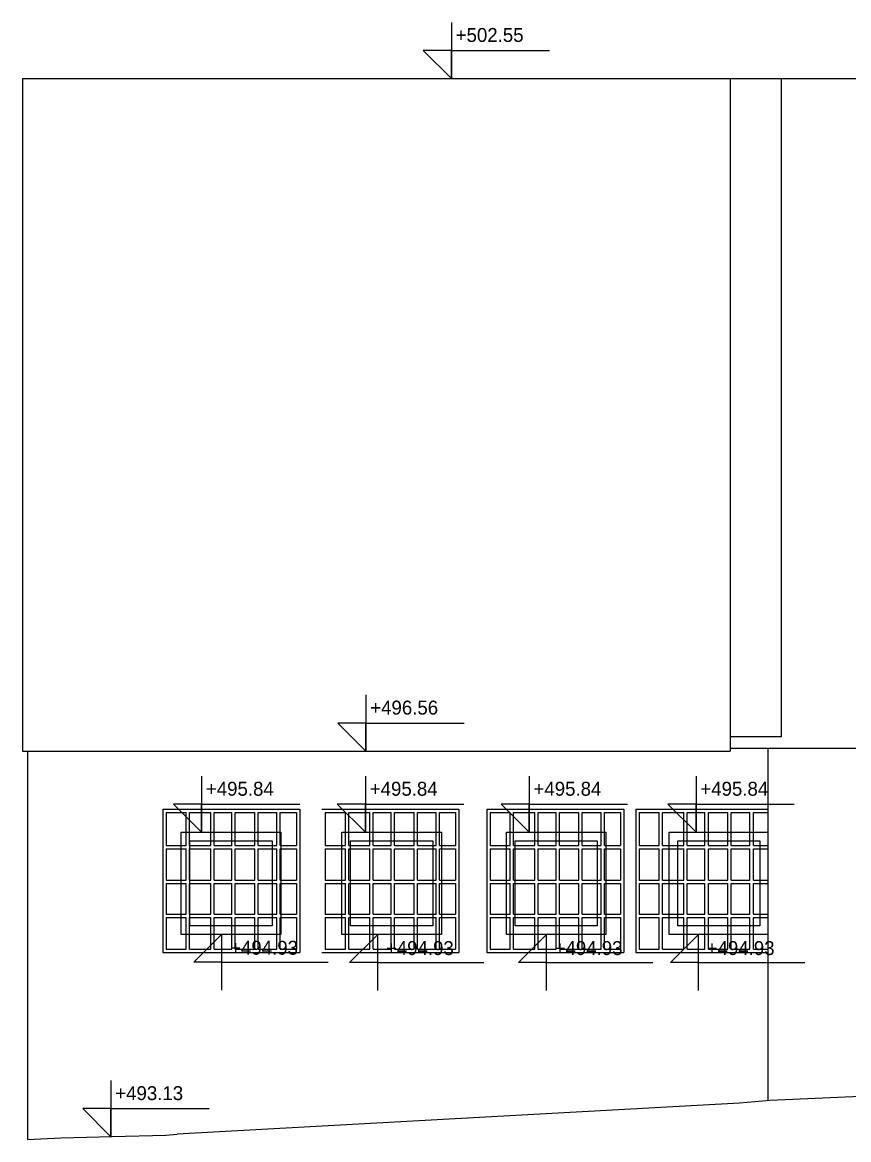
# Model space of a CAD drawing. Extents: x 224 to 311.2, y 493.1 to 511.4.
# Drawn here: x 236.11 to 243.47, y 493.1 to 503.05 of the extents above; entities that cross this region are included whole.
import ezdxf

# ---------------------------------------------------------------- set-up
doc = ezdxf.new("R2010")
doc.units = 0
for name, color, linetype in [('mriz', 7, 'Continuous'), ('okna', 7, 'Continuous'), ('teren', 7, 'Continuous'), ('zakl_tenka', 7, 'Continuous'), ('znaceni', 7, 'Continuous')]:
    doc.layers.add(name, color=color, linetype=linetype)

msp = doc.modelspace()

# ---------------------------------------------------------------- linework, layer by layer
at = {"layer": 'mriz'}
for p, q in [((237.3603, 496.0427), (237.3603, 494.7677)), ((237.3603, 496.0427), (238.5797, 496.0427)), ((237.3903, 496.0127), (237.3903, 495.7213)), ((237.3903, 496.0127), (237.5697, 496.0127)), ((237.5697, 495.7213), (237.5697, 496.0127)), ((237.5997, 496.0127), (237.7886, 496.0127)), ((237.5997, 495.7213), (237.5997, 496.0127)), ((237.7886, 495.7213), (237.7886, 496.0127)), ((237.8186, 496.0127), (237.977, 496.0127)), ((237.8186, 495.7213), (237.8186, 496.0127)), ((237.977, 495.7213), (237.977, 496.0127)), ((238.007, 496.0127), (238.1806, 496.0127)), ((238.007, 495.7213), (238.007, 496.0127)), ((238.1806, 495.7213), (238.1806, 496.0127)), ((238.2106, 496.0127), (238.3773, 496.0127)), ((238.2106, 495.7213), (238.2106, 496.0127)), ((238.3773, 495.7213), (238.3773, 496.0127)), ((238.4073, 496.0127), (238.5506, 496.0127)), ((238.4073, 495.7213), (238.4073, 496.0127)), ((238.5506, 496.0127), (238.5506, 495.7213)), ((238.5797, 496.0427), (238.5797, 494.7677)), ((238.777, 496.0427), (239.9964, 496.0427)), ((238.807, 496.0127), (238.807, 495.7213)), ((238.807, 496.0127), (238.9864, 496.0127)), ((238.9864, 495.7213), (238.9864, 496.0127)), ((239.0164, 496.0127), (239.2053, 496.0127)), ((239.0164, 495.7213), (239.0164, 496.0127)), ((239.2053, 495.7213), (239.2053, 496.0127)), ((239.2353, 496.0127), (239.3937, 496.0127)), ((239.2353, 495.7213), (239.2353, 496.0127)), ((239.3937, 495.7213), (239.3937, 496.0127)), ((239.4237, 496.0127), (239.5973, 496.0127)), ((239.4237, 495.7213), (239.4237, 496.0127)), ((239.5973, 495.7213), (239.5973, 496.0127)), ((239.6273, 496.0127), (239.794, 496.0127)), ((239.6273, 495.7213), (239.6273, 496.0127)), ((239.794, 495.7213), (239.794, 496.0127)), ((239.824, 496.0127), (239.9673, 496.0127)), ((239.824, 495.7213), (239.824, 496.0127)), ((239.9673, 496.0127), (239.9673, 495.7213)), ((239.9964, 496.0427), (239.9964, 494.7677)), ((240.245, 496.0427), (240.245, 494.7677)), ((240.245, 496.0427), (241.4645, 496.0427)), ((240.275, 496.0127), (240.275, 495.7213)), ((240.275, 496.0127), (240.4544, 496.0127)), ((240.4544, 495.7213), (240.4544, 496.0127)), ((240.4844, 496.0127), (240.6733, 496.0127)), ((240.4844, 495.7213), (240.4844, 496.0127)), ((240.6733, 495.7213), (240.6733, 496.0127)), ((240.7033, 496.0127), (240.8617, 496.0127)), ((240.7033, 495.7213), (240.7033, 496.0127)), ((240.8617, 495.7213), (240.8617, 496.0127)), ((240.8917, 496.0127), (241.0653, 496.0127)), ((240.8917, 495.7213), (240.8917, 496.0127)), ((241.0653, 495.7213), (241.0653, 496.0127)), ((241.0953, 496.0127), (241.2621, 496.0127)), ((241.0953, 495.7213), (241.0953, 496.0127)), ((241.2621, 495.7213), (241.2621, 496.0127)), ((241.2921, 496.0127), (241.4353, 496.0127)), ((241.2921, 495.7213), (241.2921, 496.0127)), ((241.4353, 496.0127), (241.4353, 495.7213)), ((241.4645, 496.0427), (241.4645, 494.7677)), ((241.5707, 496.0427), (241.5707, 494.7677)), ((241.5707, 496.0427), (242.7489, 496.0427)), ((241.6007, 496.0127), (241.6007, 495.7213)), ((241.6007, 496.0127), (241.7801, 496.0127)), ((241.7801, 495.7213), (241.7801, 496.0127)), ((241.8101, 496.0127), (241.999, 496.0127)), ((241.8101, 495.7213), (241.8101, 496.0127)), ((241.999, 495.7213), (241.999, 496.0127)), ((242.029, 496.0127), (242.1874, 496.0127)), ((242.029, 495.7213), (242.029, 496.0127)), ((242.1874, 495.7213), (242.1874, 496.0127)), ((242.2174, 496.0127), (242.3911, 496.0127)), ((242.2174, 495.7213), (242.2174, 496.0127)), ((242.3911, 495.7213), (242.3911, 496.0127)), ((242.4211, 496.0127), (242.5878, 496.0127)), ((242.4211, 495.7213), (242.4211, 496.0127)), ((242.5878, 495.7213), (242.5878, 496.0127)), ((242.6178, 496.0127), (242.7489, 496.0127)), ((242.6178, 495.7213), (242.6178, 496.0127)), ((237.3903, 495.7213), (237.5697, 495.7213)), ((237.3903, 495.6913), (237.3903, 495.4127)), ((237.3903, 495.6913), (237.5697, 495.6913)), ((237.5697, 495.4127), (237.5697, 495.6913)), ((237.5997, 495.7213), (237.7886, 495.7213)), ((237.5997, 495.4127), (237.5997, 495.6913)), ((237.5997, 495.6913), (237.7886, 495.6913)), ((237.7886, 495.4127), (237.7886, 495.6913)), ((237.8186, 495.7213), (237.977, 495.7213)), ((237.8186, 495.6913), (237.977, 495.6913)), ((237.8186, 495.4127), (237.8186, 495.6913)), ((237.977, 495.4127), (237.977, 495.6913)), ((238.007, 495.7213), (238.1806, 495.7213)), ((238.007, 495.6913), (238.1806, 495.6913)), ((238.007, 495.4127), (238.007, 495.6913)), ((238.1806, 495.4127), (238.1806, 495.6913)), ((238.2106, 495.7213), (238.3773, 495.7213)), ((238.2106, 495.6913), (238.3773, 495.6913)), ((238.2106, 495.4127), (238.2106, 495.6913)), ((238.3773, 495.4127), (238.3773, 495.6913)), ((238.4073, 495.7213), (238.5506, 495.7213)), ((238.4073, 495.6913), (238.5506, 495.6913)), ((238.4073, 495.4127), (238.4073, 495.6913)), ((238.5506, 495.6913), (238.5506, 495.4127)), ((238.807, 495.7213), (238.9864, 495.7213)), ((238.807, 495.6913), (238.807, 495.4127)), ((238.807, 495.6913), (238.9864, 495.6913)), ((238.9864, 495.4127), (238.9864, 495.6913)), ((239.0164, 495.7213), (239.2053, 495.7213)), ((239.0164, 495.4127), (239.0164, 495.6913)), ((239.0164, 495.6913), (239.2053, 495.6913)), ((239.2053, 495.4127), (239.2053, 495.6913)), ((239.2353, 495.7213), (239.3937, 495.7213)), ((239.2353, 495.6913), (239.3937, 495.6913)), ((239.2353, 495.4127), (239.2353, 495.6913)), ((239.3937, 495.4127), (239.3937, 495.6913)), ((239.4237, 495.7213), (239.5973, 495.7213)), ((239.4237, 495.6913), (239.5973, 495.6913)), ((239.4237, 495.4127), (239.4237, 495.6913)), ((239.5973, 495.4127), (239.5973, 495.6913)), ((239.6273, 495.7213), (239.794, 495.7213)), ((239.6273, 495.6913), (239.794, 495.6913)), ((239.6273, 495.4127), (239.6273, 495.6913)), ((239.794, 495.4127), (239.794, 495.6913)), ((239.824, 495.7213), (239.9673, 495.7213)), ((239.824, 495.6913), (239.9673, 495.6913)), ((239.824, 495.4127), (239.824, 495.6913)), ((239.9673, 495.6913), (239.9673, 495.4127)), ((240.275, 495.7213), (240.4544, 495.7213)), ((240.275, 495.6913), (240.275, 495.4127)), ((240.275, 495.6913), (240.4544, 495.6913)), ((240.4544, 495.4127), (240.4544, 495.6913)), ((240.4844, 495.7213), (240.6733, 495.7213)), ((240.4844, 495.4127), (240.4844, 495.6913)), ((240.4844, 495.6913), (240.6733, 495.6913)), ((240.6733, 495.4127), (240.6733, 495.6913)), ((240.7033, 495.7213), (240.8617, 495.7213)), ((240.7033, 495.6913), (240.8617, 495.6913)), ((240.7033, 495.4127), (240.7033, 495.6913)), ((240.8617, 495.4127), (240.8617, 495.6913)), ((240.8917, 495.7213), (241.0653, 495.7213)), ((240.8917, 495.6913), (241.0653, 495.6913)), ((240.8917, 495.4127), (240.8917, 495.6913)), ((241.0653, 495.4127), (241.0653, 495.6913)), ((241.0953, 495.7213), (241.2621, 495.7213)), ((241.0953, 495.6913), (241.2621, 495.6913)), ((241.0953, 495.4127), (241.0953, 495.6913)), ((241.2621, 495.4127), (241.2621, 495.6913)), ((241.2921, 495.7213), (241.4353, 495.7213)), ((241.2921, 495.6913), (241.4353, 495.6913)), ((241.2921, 495.4127), (241.2921, 495.6913)), ((241.4353, 495.6913), (241.4353, 495.4127)), ((241.6007, 495.7213), (241.7801, 495.7213)), ((241.6007, 495.6913), (241.6007, 495.4127)), ((241.6007, 495.6913), (241.7801, 495.6913)), ((241.7801, 495.4127), (241.7801, 495.6913)), ((241.8101, 495.7213), (241.999, 495.7213)), ((241.8101, 495.4127), (241.8101, 495.6913)), ((241.8101, 495.6913), (241.999, 495.6913)), ((241.999, 495.4127), (241.999, 495.6913)), ((242.029, 495.7213), (242.1874, 495.7213)), ((242.029, 495.6913), (242.1874, 495.6913)), ((242.029, 495.4127), (242.029, 495.6913)), ((242.1874, 495.4127), (242.1874, 495.6913)), ((242.2174, 495.7213), (242.3911, 495.7213)), ((242.2174, 495.6913), (242.3911, 495.6913)), ((242.2174, 495.4127), (242.2174, 495.6913)), ((242.3911, 495.4127), (242.3911, 495.6913)), ((242.4211, 495.7213), (242.5878, 495.7213)), ((242.4211, 495.6913), (242.5878, 495.6913)), ((242.4211, 495.4127), (242.4211, 495.6913)), ((242.5878, 495.4127), (242.5878, 495.6913)), ((242.6178, 495.7213), (242.7489, 495.7213)), ((242.6178, 495.6913), (242.7489, 495.6913)), ((242.6178, 495.4127), (242.6178, 495.6913)), ((237.3903, 495.4127), (237.5697, 495.4127)), ((237.5997, 495.4127), (237.7886, 495.4127)), ((237.8186, 495.4127), (237.977, 495.4127)), ((238.007, 495.4127), (238.1806, 495.4127)), ((238.2106, 495.4127), (238.3773, 495.4127)), ((238.4073, 495.4127), (238.5506, 495.4127)), ((238.807, 495.4127), (238.9864, 495.4127)), ((239.0164, 495.4127), (239.2053, 495.4127)), ((239.2353, 495.4127), (239.3937, 495.4127)), ((239.4237, 495.4127), (239.5973, 495.4127)), ((239.6273, 495.4127), (239.794, 495.4127)), ((239.824, 495.4127), (239.9673, 495.4127)), ((240.275, 495.4127), (240.4544, 495.4127)), ((240.4844, 495.4127), (240.6733, 495.4127)), ((240.7033, 495.4127), (240.8617, 495.4127)), ((240.8917, 495.4127), (241.0653, 495.4127)), ((241.0953, 495.4127), (241.2621, 495.4127)), ((241.2921, 495.4127), (241.4353, 495.4127)), ((241.6007, 495.4127), (241.7801, 495.4127)), ((241.8101, 495.4127), (241.999, 495.4127)), ((242.029, 495.4127), (242.1874, 495.4127)), ((242.2174, 495.4127), (242.3911, 495.4127)), ((242.4211, 495.4127), (242.5878, 495.4127)), ((242.6178, 495.4127), (242.7489, 495.4127)), ((237.3903, 495.3827), (237.3903, 495.1087)), ((237.3903, 495.3827), (237.5697, 495.3827)), ((237.5697, 495.1087), (237.5697, 495.3827)), ((237.5997, 495.3827), (237.7886, 495.3827)), ((237.5997, 495.1087), (237.5997, 495.3827)), ((237.7886, 495.1087), (237.7886, 495.3827)), ((237.8186, 495.3827), (237.977, 495.3827)), ((237.8186, 495.1087), (237.8186, 495.3827)), ((237.977, 495.1087), (237.977, 495.3827)), ((238.007, 495.3827), (238.1806, 495.3827)), ((238.007, 495.1087), (238.007, 495.3827)), ((238.1806, 495.1087), (238.1806, 495.3827)), ((238.2106, 495.3827), (238.3773, 495.3827)), ((238.2106, 495.1087), (238.2106, 495.3827)), ((238.3773, 495.1087), (238.3773, 495.3827)), ((238.4073, 495.3827), (238.5506, 495.3827)), ((238.4073, 495.1087), (238.4073, 495.3827)), ((238.5506, 495.3827), (238.5506, 495.1087)), ((238.807, 495.3827), (238.807, 495.1087)), ((238.807, 495.3827), (238.9864, 495.3827)), ((238.9864, 495.1087), (238.9864, 495.3827)), ((239.0164, 495.3827), (239.2053, 495.3827)), ((239.0164, 495.1087), (239.0164, 495.3827)), ((239.2053, 495.1087), (239.2053, 495.3827)), ((239.2353, 495.3827), (239.3937, 495.3827)), ((239.2353, 495.1087), (239.2353, 495.3827)), ((239.3937, 495.1087), (239.3937, 495.3827)), ((239.4237, 495.3827), (239.5973, 495.3827)), ((239.4237, 495.1087), (239.4237, 495.3827)), ((239.5973, 495.1087), (239.5973, 495.3827)), ((239.6273, 495.3827), (239.794, 495.3827)), ((239.6273, 495.1087), (239.6273, 495.3827)), ((239.794, 495.1087), (239.794, 495.3827)), ((239.824, 495.3827), (239.9673, 495.3827)), ((239.824, 495.1087), (239.824, 495.3827)), ((239.9673, 495.3827), (239.9673, 495.1087)), ((240.275, 495.3827), (240.275, 495.1087)), ((240.275, 495.3827), (240.4544, 495.3827)), ((240.4544, 495.1087), (240.4544, 495.3827)), ((240.4844, 495.3827), (240.6733, 495.3827)), ((240.4844, 495.1087), (240.4844, 495.3827)), ((240.6733, 495.1087), (240.6733, 495.3827)), ((240.7033, 495.3827), (240.8617, 495.3827)), ((240.7033, 495.1087), (240.7033, 495.3827)), ((240.8617, 495.1087), (240.8617, 495.3827)), ((240.8917, 495.3827), (241.0653, 495.3827)), ((240.8917, 495.1087), (240.8917, 495.3827)), ((241.0653, 495.1087), (241.0653, 495.3827)), ((241.0953, 495.3827), (241.2621, 495.3827)), ((241.0953, 495.1087), (241.0953, 495.3827)), ((241.2621, 495.1087), (241.2621, 495.3827)), ((241.2921, 495.3827), (241.4353, 495.3827)), ((241.2921, 495.1087), (241.2921, 495.3827)), ((241.4353, 495.3827), (241.4353, 495.1087)), ((241.6007, 495.3827), (241.6007, 495.1087)), ((241.6007, 495.3827), (241.7801, 495.3827)), ((241.7801, 495.1087), (241.7801, 495.3827)), ((241.8101, 495.3827), (241.999, 495.3827)), ((241.8101, 495.1087), (241.8101, 495.3827)), ((241.999, 495.1087), (241.999, 495.3827)), ((242.029, 495.3827), (242.1874, 495.3827)), ((242.029, 495.1087), (242.029, 495.3827)), ((242.1874, 495.1087), (242.1874, 495.3827)), ((242.2174, 495.3827), (242.3911, 495.3827)), ((242.2174, 495.1087), (242.2174, 495.3827)), ((242.3911, 495.1087), (242.3911, 495.3827)), ((242.4211, 495.3827), (242.5878, 495.3827)), ((242.4211, 495.1087), (242.4211, 495.3827)), ((242.5878, 495.1087), (242.5878, 495.3827)), ((242.6178, 495.3827), (242.7489, 495.3827)), ((242.6178, 495.1087), (242.6178, 495.3827)), ((237.3903, 495.1087), (237.5697, 495.1087)), ((237.5997, 495.1087), (237.7886, 495.1087)), ((237.8186, 495.1087), (237.977, 495.1087)), ((238.007, 495.1087), (238.1806, 495.1087)), ((238.2106, 495.1087), (238.3773, 495.1087)), ((238.4073, 495.1087), (238.5506, 495.1087)), ((238.807, 495.1087), (238.9864, 495.1087)), ((239.0164, 495.1087), (239.2053, 495.1087)), ((239.2353, 495.1087), (239.3937, 495.1087)), ((239.4237, 495.1087), (239.5973, 495.1087)), ((239.6273, 495.1087), (239.794, 495.1087)), ((239.824, 495.1087), (239.9673, 495.1087)), ((240.275, 495.1087), (240.4544, 495.1087)), ((240.4844, 495.1087), (240.6733, 495.1087)), ((240.7033, 495.1087), (240.8617, 495.1087)), ((240.8917, 495.1087), (241.0653, 495.1087)), ((241.0953, 495.1087), (241.2621, 495.1087)), ((241.2921, 495.1087), (241.4353, 495.1087)), ((241.6007, 495.1087), (241.7801, 495.1087)), ((241.8101, 495.1087), (241.999, 495.1087)), ((242.029, 495.1087), (242.1874, 495.1087)), ((242.2174, 495.1087), (242.3911, 495.1087)), ((242.4211, 495.1087), (242.5878, 495.1087)), ((242.6178, 495.1087), (242.7489, 495.1087)), ((237.3903, 495.0787), (237.3903, 494.7977)), ((237.3903, 495.0787), (237.5697, 495.0787)), ((237.5697, 494.7977), (237.5697, 495.0787)), ((237.5997, 494.7977), (237.5997, 495.0787)), ((237.5997, 495.0787), (237.7886, 495.0787)), ((237.7886, 494.7977), (237.7886, 495.0787)), ((237.8186, 494.7977), (237.8186, 495.0787)), ((237.8186, 495.0787), (237.977, 495.0787)), ((237.977, 494.7977), (237.977, 495.0787)), ((238.007, 494.7977), (238.007, 495.0787)), ((238.007, 495.0787), (238.1806, 495.0787)), ((238.1806, 494.7977), (238.1806, 495.0787)), ((238.2106, 494.7977), (238.2106, 495.0787)), ((238.2106, 495.0787), (238.3773, 495.0787)), ((238.3773, 494.7977), (238.3773, 495.0787)), ((238.4073, 494.7977), (238.4073, 495.0787)), ((238.4073, 495.0787), (238.5506, 495.0787)), ((238.5506, 495.0787), (238.5506, 494.7977)), ((238.807, 495.0787), (238.807, 494.7977)), ((238.807, 495.0787), (238.9864, 495.0787)), ((238.9864, 494.7977), (238.9864, 495.0787)), ((239.0164, 494.7977), (239.0164, 495.0787)), ((239.0164, 495.0787), (239.2053, 495.0787)), ((239.2053, 494.7977), (239.2053, 495.0787)), ((239.2353, 494.7977), (239.2353, 495.0787)), ((239.2353, 495.0787), (239.3937, 495.0787)), ((239.3937, 494.7977), (239.3937, 495.0787)), ((239.4237, 494.7977), (239.4237, 495.0787)), ((239.4237, 495.0787), (239.5973, 495.0787)), ((239.5973, 494.7977), (239.5973, 495.0787)), ((239.6273, 494.7977), (239.6273, 495.0787)), ((239.6273, 495.0787), (239.794, 495.0787)), ((239.794, 494.7977), (239.794, 495.0787)), ((239.824, 494.7977), (239.824, 495.0787)), ((239.824, 495.0787), (239.9673, 495.0787)), ((239.9673, 495.0787), (239.9673, 494.7977)), ((240.275, 495.0787), (240.275, 494.7977)), ((240.275, 495.0787), (240.4544, 495.0787)), ((240.4544, 494.7977), (240.4544, 495.0787)), ((240.4844, 494.7977), (240.4844, 495.0787)), ((240.4844, 495.0787), (240.6733, 495.0787)), ((240.6733, 494.7977), (240.6733, 495.0787)), ((240.7033, 494.7977), (240.7033, 495.0787)), ((240.7033, 495.0787), (240.8617, 495.0787)), ((240.8617, 494.7977), (240.8617, 495.0787)), ((240.8917, 494.7977), (240.8917, 495.0787)), ((240.8917, 495.0787), (241.0653, 495.0787)), ((241.0653, 494.7977), (241.0653, 495.0787)), ((241.0953, 494.7977), (241.0953, 495.0787)), ((241.0953, 495.0787), (241.2621, 495.0787)), ((241.2621, 494.7977), (241.2621, 495.0787)), ((241.2921, 494.7977), (241.2921, 495.0787)), ((241.2921, 495.0787), (241.4353, 495.0787)), ((241.4353, 495.0787), (241.4353, 494.7977)), ((241.6007, 495.0787), (241.6007, 494.7977)), ((241.6007, 495.0787), (241.7801, 495.0787)), ((241.7801, 494.7977), (241.7801, 495.0787)), ((241.8101, 494.7977), (241.8101, 495.0787)), ((241.8101, 495.0787), (241.999, 495.0787)), ((241.999, 494.7977), (241.999, 495.0787)), ((242.029, 494.7977), (242.029, 495.0787)), ((242.029, 495.0787), (242.1874, 495.0787)), ((242.1874, 494.7977), (242.1874, 495.0787)), ((242.2174, 494.7977), (242.2174, 495.0787)), ((242.2174, 495.0787), (242.3911, 495.0787)), ((242.3911, 494.7977), (242.3911, 495.0787)), ((242.4211, 494.7977), (242.4211, 495.0787)), ((242.4211, 495.0787), (242.5878, 495.0787)), ((242.5878, 494.7977), (242.5878, 495.0787)), ((242.6178, 494.7977), (242.6178, 495.0787)), ((242.6178, 495.0787), (242.7489, 495.0787)), ((237.3903, 494.7977), (237.5697, 494.7977)), ((237.5997, 494.7977), (237.7886, 494.7977)), ((237.8186, 494.7977), (237.977, 494.7977)), ((238.007, 494.7977), (238.1806, 494.7977)), ((238.2106, 494.7977), (238.3773, 494.7977)), ((238.4073, 494.7977), (238.5506, 494.7977)), ((238.807, 494.7977), (238.9864, 494.7977)), ((239.0164, 494.7977), (239.2053, 494.7977)), ((239.2353, 494.7977), (239.3937, 494.7977)), ((239.4237, 494.7977), (239.5973, 494.7977)), ((239.6273, 494.7977), (239.794, 494.7977)), ((239.824, 494.7977), (239.9673, 494.7977)), ((240.275, 494.7977), (240.4544, 494.7977)), ((240.4844, 494.7977), (240.6733, 494.7977)), ((240.7033, 494.7977), (240.8617, 494.7977)), ((240.8917, 494.7977), (241.0653, 494.7977)), ((241.0953, 494.7977), (241.2621, 494.7977)), ((241.2921, 494.7977), (241.4353, 494.7977)), ((241.6007, 494.7977), (241.7801, 494.7977)), ((241.8101, 494.7977), (241.999, 494.7977)), ((242.029, 494.7977), (242.1874, 494.7977)), ((242.2174, 494.7977), (242.3911, 494.7977)), ((242.4211, 494.7977), (242.5878, 494.7977)), ((242.6178, 494.7977), (242.7489, 494.7977)), ((237.3603, 494.7677), (238.5797, 494.7677)), ((238.777, 494.7677), (239.9964, 494.7677)), ((240.245, 494.7677), (241.4645, 494.7677)), ((241.5707, 494.7677), (242.7489, 494.7677))]:
    msp.add_line(p, q, dxfattribs=at)
at = {"layer": 'okna'}
for points in [[(237.6028, 495.7608), (238.3343, 495.7608), (238.3343, 495.0058), (237.6028, 495.0058)], [(239.0332, 495.7608), (239.7646, 495.7608), (239.7646, 495.0058), (239.0332, 495.0058)], [(240.4974, 495.7608), (241.2289, 495.7608), (241.2289, 495.0058), (240.4974, 495.0058)], [(241.9444, 495.7608), (242.6758, 495.7608), (242.6758, 495.0058), (241.9444, 495.0058)]]:
    msp.add_lwpolyline(points, close=True, dxfattribs=at)
at = {"layer": 'teren'}
for points in [[(255.2621, 493.8982), (251.8099, 493.7874), (245.7062, 493.5796), (242.7666, 493.4494), (242.495, 493.4272), (237.4899, 493.1488)], [(236.1574, 493.1013), (236.453, 493.1176), (236.9095, 493.128), (237.3888, 493.1419), (237.4899, 493.1488)]]:
    msp.add_lwpolyline(points, dxfattribs=at)
at = {"layer": 'zakl_tenka'}
for p, q in [((236.1114, 502.5488), (236.1114, 496.5605)), ((236.1114, 502.5488), (243.8738, 502.5488)), ((242.4126, 502.5488), (242.4126, 496.5605)), ((242.866, 502.5488), (242.866, 496.6886)), ((242.866, 496.6886), (242.4126, 496.6886)), ((242.4126, 496.5882), (255.8623, 496.5882)), ((242.7489, 493.4511), (242.7489, 496.5882)), ((236.1114, 496.5605), (242.4126, 496.5605)), ((236.1574, 496.5605), (236.1574, 493.1013))]:
    msp.add_line(p, q, dxfattribs=at)
for points in [[(237.5259, 495.8377), (238.4111, 495.8377), (238.4111, 494.9289), (237.5259, 494.9289)], [(238.9563, 495.8377), (239.8415, 495.8377), (239.8415, 494.9289), (238.9563, 494.9289)], [(240.4205, 495.8377), (241.3058, 495.8377), (241.3058, 494.9289), (240.4205, 494.9289)]]:
    msp.add_lwpolyline(points, close=True, dxfattribs=at)
msp.add_lwpolyline([(242.7489, 494.9289), (241.8675, 494.9289), (241.8675, 495.8377), (242.7489, 495.8377)], dxfattribs=at)
at = {"layer": 'znaceni'}
for p, q in [((239.9296, 503.0488), (239.9296, 502.5488)), ((239.9296, 502.7988), (239.6796, 502.7988)), ((239.6796, 502.7988), (239.9296, 502.5488)), ((239.9296, 502.7988), (240.8046, 502.7988)), ((239.9296, 502.5488), (239.9296, 502.7988)), ((239.1691, 497.0605), (239.1691, 496.5605)), ((239.1691, 496.8105), (238.9191, 496.8105)), ((238.9191, 496.8105), (239.1691, 496.5605)), ((239.1691, 496.8105), (240.044, 496.8105)), ((239.1691, 496.5605), (239.1691, 496.8105)), ((237.7062, 496.3377), (237.7062, 495.8377)), ((239.1649, 496.3377), (239.1649, 495.8377)), ((240.6223, 496.3377), (240.6223, 495.8377)), ((242.1073, 496.3377), (242.1073, 495.8377)), ((237.7062, 496.0877), (237.4562, 496.0877)), ((237.4562, 496.0877), (237.7062, 495.8377)), ((237.7062, 496.0877), (238.5811, 496.0877)), ((237.7062, 495.8377), (237.7062, 496.0877)), ((239.1649, 496.0877), (238.9149, 496.0877)), ((238.9149, 496.0877), (239.1649, 495.8377)), ((239.1649, 496.0877), (240.0399, 496.0877)), ((239.1649, 495.8377), (239.1649, 496.0877)), ((240.6223, 496.0877), (240.3723, 496.0877)), ((240.3723, 496.0877), (240.6223, 495.8377)), ((240.6223, 496.0877), (241.4972, 496.0877)), ((240.6223, 495.8377), (240.6223, 496.0877)), ((242.1073, 496.0877), (241.8573, 496.0877)), ((241.8573, 496.0877), (242.1073, 495.8377)), ((242.1073, 496.0877), (242.9823, 496.0877)), ((242.1073, 495.8377), (242.1073, 496.0877)), ((237.6377, 494.6817), (237.8877, 494.9317)), ((237.8877, 494.4317), (237.8877, 494.9317)), ((239.0244, 494.6789), (239.2744, 494.9289)), ((239.2744, 494.4289), (239.2744, 494.9289)), ((240.526, 494.6789), (240.776, 494.9289)), ((240.776, 494.4289), (240.776, 494.9289)), ((241.8795, 494.6789), (242.1295, 494.9289)), ((242.1295, 494.4289), (242.1295, 494.9289)), ((237.8877, 494.6817), (237.6377, 494.6817)), ((237.8877, 494.6817), (238.8332, 494.6817)), ((239.2744, 494.6789), (239.0244, 494.6789)), ((239.2744, 494.6789), (240.2199, 494.6789)), ((240.776, 494.6789), (240.526, 494.6789)), ((240.776, 494.6789), (241.7216, 494.6789)), ((242.1295, 494.6789), (241.8795, 494.6789)), ((242.1295, 494.6789), (243.075, 494.6789)), ((236.8994, 493.6278), (236.8994, 493.1278)), ((236.8994, 493.3778), (236.6494, 493.3778)), ((236.6494, 493.3778), (236.8994, 493.1278)), ((236.8994, 493.3778), (237.7743, 493.3778)), ((236.8994, 493.1278), (236.8994, 493.3778))]:
    msp.add_line(p, q, dxfattribs=at)

# ---------------------------------------------------------------- texts
for s, p in [('+502.55', (239.9684, 502.8744)), ('+496.56', (239.2079, 496.8861)), ('+495.84', (237.745, 496.1633)), ('+495.84', (239.2037, 496.1633)), ('+495.84', (240.6611, 496.1633)), ('+495.84', (242.1461, 496.1633)), ('+494.93', (237.9607, 494.7477)), ('+494.93', (239.3474, 494.745)), ('+494.93', (240.8491, 494.745)), ('+494.93', (242.2026, 494.745)), ('+493.13', (236.9382, 493.4534))]:
    msp.add_text(s, height=0.124, dxfattribs=at).set_placement(p)

doc.saveas('drawing.dxf')
